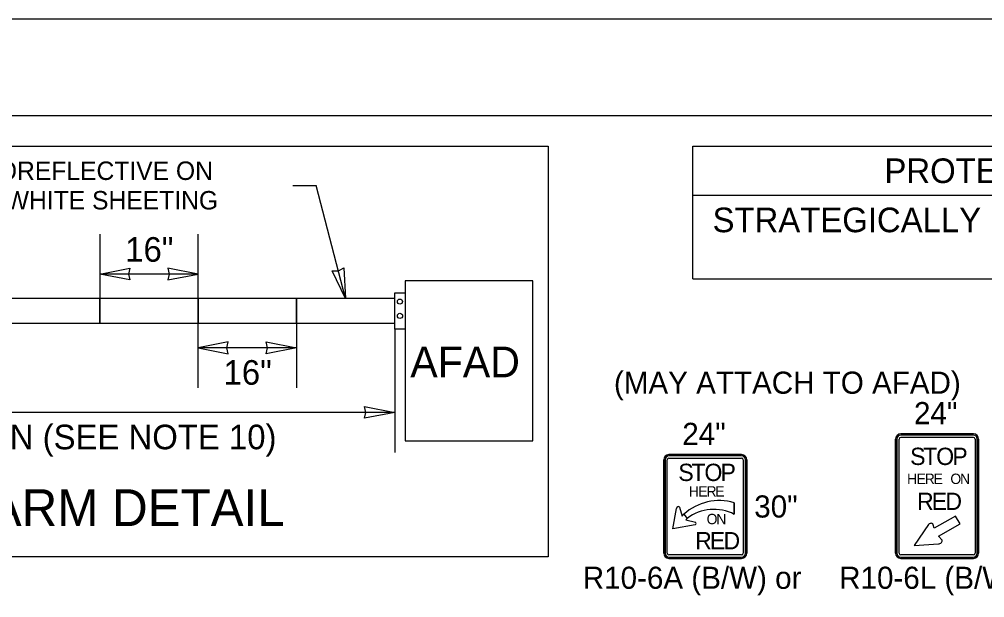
# Model space of a CAD drawing. Extents: x 99999.1 to 100095.7, y 99995 to 100010.7.
# Drawn here: x 100009.243 to 100012.384, y 100008.806 to 100010.687 of the extents above; entities that cross this region are included whole.
import ezdxf

# ---------------------------------------------------------------- set-up
doc = ezdxf.new("R2010")
doc.units = 0
for name, color, linetype in [('SH_GI_PlotLimits', 7, 'Continuous'), ('SH_GI_SheetBorder', 7, 'Continuous'), ('SH_TI_Tables', 7, 'Continuous'), ('TR_SN_ConstructionSigns', 7, 'Continuous'), ('TR_WZ_WorkZoneDetails', 7, 'Continuous')]:
    doc.layers.add(name, color=color, linetype=linetype)

msp = doc.modelspace()

# ---------------------------------------------------------------- linework, layer by layer
at = {"layer": 'SH_GI_PlotLimits'}
msp.add_lwpolyline([(99999.0625, 99999.6875), (100016.0625, 99999.6875), (100016.0625, 100010.6875), (99999.0625, 100010.6875)], close=True, dxfattribs=at)
at = {"layer": 'SH_GI_SheetBorder'}
msp.add_line((100000, 100010.375), (100015.75, 100010.375), dxfattribs=at)
at = {"layer": 'SH_TI_Tables'}
for p, q in [((100011.4347, 100009.843), (100011.4347, 100010.275)), ((100011.4347, 100010.275), (100015.65, 100010.275)), ((100011.4347, 100010.115), (100015.65, 100010.115)), ((100011.4347, 100009.843), (100015.65, 100009.843))]:
    msp.add_line(p, q, dxfattribs=at)
at = {"layer": 'TR_SN_ConstructionSigns'}
for p, q in [((100012.0939, 100009.3222), (100012.0939, 100008.951)), ((100012.0939, 100008.951), (100012.0939, 100009.3222)), ((100012.0939, 100009.3222), (100012.0939, 100008.951)), ((100012.0981, 100009.3222), (100012.0981, 100008.951)), ((100012.1052, 100008.951), (100012.1052, 100009.3222)), ((100012.347, 100009.3391), (100012.1108, 100009.3391)), ((100012.1108, 100009.3391), (100012.347, 100009.3391)), ((100012.347, 100009.3391), (100012.1108, 100009.3391)), ((100012.347, 100009.3349), (100012.1108, 100009.3349)), ((100012.1108, 100009.3279), (100012.347, 100009.3279)), ((100012.3527, 100009.3222), (100012.3527, 100008.951)), ((100012.3597, 100008.951), (100012.3597, 100009.3222)), ((100012.3639, 100008.951), (100012.3639, 100009.3222)), ((100012.3639, 100009.3222), (100012.3639, 100008.951)), ((100012.3639, 100008.951), (100012.3639, 100009.3222)), ((100011.3397, 100009.2547), (100011.3397, 100008.951)), ((100011.3397, 100008.951), (100011.3397, 100009.2547)), ((100011.3397, 100009.2547), (100011.3397, 100008.951)), ((100011.3397, 100008.951), (100011.3397, 100009.2547)), ((100011.3439, 100009.2547), (100011.3439, 100008.951)), ((100011.351, 100008.951), (100011.351, 100009.2547)), ((100011.5928, 100009.2716), (100011.3566, 100009.2716)), ((100011.3566, 100009.2716), (100011.5928, 100009.2716)), ((100011.5928, 100009.2716), (100011.3566, 100009.2716)), ((100011.3566, 100009.2716), (100011.5928, 100009.2716)), ((100011.5928, 100009.2674), (100011.3566, 100009.2674)), ((100011.3566, 100009.2604), (100011.5928, 100009.2604)), ((100011.5985, 100009.2547), (100011.5985, 100008.951)), ((100011.6055, 100008.951), (100011.6055, 100009.2547)), ((100011.6097, 100008.951), (100011.6097, 100009.2547)), ((100011.6097, 100009.2547), (100011.6097, 100008.951)), ((100011.6097, 100008.951), (100011.6097, 100009.2547)), ((100011.6097, 100009.2547), (100011.6097, 100008.951)), ((100011.3692, 100009.0297), (100011.3815, 100009.0967)), ((100011.3912, 100009.1011), (100011.3997, 100009.0719)), ((100011.5692, 100009.1152), (100011.5689, 100009.0774)), ((100011.5689, 100009.0774), (100011.5692, 100009.1152)), ((100011.3997, 100009.0719), (100011.4054, 100009.0776)), ((100011.4054, 100009.0776), (100011.4159, 100009.0642)), ((100011.4054, 100009.0776), (100011.4159, 100009.0642)), ((100011.4159, 100009.0642), (100011.4117, 100009.0599)), ((100012.289, 100009.0719), (100012.22, 100009.0321)), ((100012.3037, 100009.0463), (100012.289, 100009.0719)), ((100011.4423, 100009.0433), (100011.3692, 100009.0297)), ((100011.4117, 100009.0599), (100011.4424, 100009.0517)), ((100012.2015, 100009.0445), (100012.1541, 100008.9764)), ((100012.22, 100009.0321), (100012.2166, 100009.0435)), ((100012.234, 100009.0061), (100012.3037, 100009.0463)), ((100012.2451, 100008.9938), (100012.234, 100009.0061)), ((100012.1541, 100008.9764), (100012.2332, 100008.9819)), ((100011.5928, 100008.9454), (100011.3566, 100008.9454)), ((100011.3566, 100008.9383), (100011.5928, 100008.9383)), ((100012.347, 100008.9454), (100012.1108, 100008.9454)), ((100012.1108, 100008.9383), (100012.347, 100008.9383)), ((100011.3566, 100008.9341), (100011.5928, 100008.9341)), ((100011.5928, 100008.9341), (100011.3566, 100008.9341)), ((100011.3566, 100008.9341), (100011.5928, 100008.9341)), ((100011.5928, 100008.9341), (100011.3566, 100008.9341)), ((100012.1108, 100008.9341), (100012.347, 100008.9341)), ((100012.347, 100008.9341), (100012.1108, 100008.9341)), ((100012.1108, 100008.9341), (100012.347, 100008.9341))]:
    msp.add_line(p, q, dxfattribs=at)
for centre, radius, start, end in [((100012.1108, 100009.3222), 0.0169, 90, 180), ((100012.1108, 100009.3222), 0.0169, 90, 180), ((100012.1108, 100009.3222), 0.0169, 90, 180), ((100012.1108, 100009.3222), 0.0127, 90, 180), ((100012.1108, 100009.3222), 0.00562, 90, 180), ((100012.347, 100009.3222), 0.0169, 0, 90), ((100012.347, 100009.3222), 0.0169, 0, 90), ((100012.347, 100009.3222), 0.0169, 0, 90), ((100012.347, 100009.3222), 0.0127, 0, 90), ((100012.347, 100009.3222), 0.00562, 0, 90), ((100011.3566, 100009.2547), 0.0169, 90, 180), ((100011.3566, 100009.2547), 0.0169, 90, 180), ((100011.3566, 100009.2547), 0.0169, 90, 180), ((100011.3566, 100009.2547), 0.0169, 90, 180), ((100011.3566, 100009.2547), 0.0127, 90, 180), ((100011.3566, 100009.2547), 0.00562, 90, 180), ((100011.5928, 100009.2547), 0.0169, 0, 90), ((100011.5928, 100009.2547), 0.0169, 0, 90), ((100011.5928, 100009.2547), 0.0169, 0, 90), ((100011.5928, 100009.2547), 0.0169, 0, 90), ((100011.5928, 100009.2547), 0.0127, 0, 90), ((100011.5928, 100009.2547), 0.00562, 0, 90), ((100011.5208, 100008.9504), 0.1718, 73.6434, 132.2131), ((100011.5208, 100008.9504), 0.1718, 73.6434, 132.2131), ((100011.5028, 100008.9509), 0.1427, 62.4149, 127.4769), ((100011.5028, 100008.9509), 0.1427, 62.4149, 127.4769), ((100011.3566, 100008.951), 0.0169, 180, 270), ((100011.3566, 100008.951), 0.0169, 180, 270), ((100011.3566, 100008.951), 0.0169, 180, 270), ((100011.3566, 100008.951), 0.0169, 180, 270), ((100011.3566, 100008.951), 0.0127, 180, 270), ((100011.3566, 100008.951), 0.00562, 180, 270), ((100011.5928, 100008.951), 0.0169, 270, 0), ((100011.5928, 100008.951), 0.0169, 270, 0), ((100011.5928, 100008.951), 0.0169, 270, 0), ((100011.5928, 100008.951), 0.0127, 270, 0), ((100011.5928, 100008.951), 0.00562, 270, 0), ((100011.5928, 100008.951), 0.0169, 270, 0), ((100012.1108, 100008.951), 0.0169, 180, 270), ((100012.1108, 100008.951), 0.0169, 180, 270), ((100012.1108, 100008.951), 0.0169, 180, 270), ((100012.1108, 100008.951), 0.0127, 180, 270), ((100012.1108, 100008.951), 0.00562, 180, 270), ((100012.347, 100008.951), 0.0169, 270, 0), ((100012.347, 100008.951), 0.0169, 270, 0), ((100012.347, 100008.951), 0.0169, 270, 0), ((100012.347, 100008.951), 0.0127, 270, 0), ((100012.347, 100008.951), 0.00562, 270, 0)]:
    msp.add_arc(centre, radius, start, end, dxfattribs=at)
for centre, major_axis, ratio, start_param, end_param in [((100011.3873, 100009.0968), (-0.00583, -0.00008), 0.989437, 3.962549, 6.283185), ((100011.4403, 100009.0475), (-0.00414, 0.00215), 0.999053, 2.490568, 4.712389), ((100012.2076, 100009.0406), (0.00841, 0.00485), 0.700347, 5.977036, 8.198856), ((100012.2368, 100008.9893), (-0.00822, -0.00474), 0.700347, 0.771965, 3.092601)]:
    msp.add_ellipse(centre, major_axis=major_axis, ratio=ratio, start_param=start_param, end_param=end_param, dxfattribs=at)
at = {"layer": 'TR_WZ_WorkZoneDetails'}
for p, q in [((100010.1326, 100010.147), (100010.2088, 100010.147)), ((100010.3043, 100009.779), (100010.2088, 100010.147)), ((100009.5043, 100009.989), (100009.5043, 100009.779)), ((100009.8243, 100009.779), (100009.8243, 100009.989)), ((100009.8243, 100009.859), (100009.5043, 100009.859)), ((100009.8243, 100009.489), (100009.8243, 100009.699)), ((100010.1443, 100009.699), (100010.1443, 100009.489)), ((100010.4643, 100009.6797), (100010.4643, 100009.279)), ((100010.1443, 100009.619), (100009.8243, 100009.619)), ((100010.4643, 100009.409), (100008.6643, 100009.409))]:
    msp.add_line(p, q, dxfattribs=at)
for points in [[(100007.6374, 100010.275), (100010.9639, 100010.275), (100010.9639, 100008.939), (100007.6374, 100008.939)], [(100009.5043, 100009.859), (100009.6026, 100009.8783), (100009.5981, 100009.859), (100009.6026, 100009.8397)], [(100009.8243, 100009.859), (100009.7261, 100009.8783), (100009.7306, 100009.859), (100009.7261, 100009.8397)], [(100010.3043, 100009.779), (100010.2611, 100009.8693), (100010.2809, 100009.8697), (100010.2984, 100009.879)], [(100010.4643, 100009.7983), (100010.4977, 100009.7983), (100010.4977, 100009.6797), (100010.4643, 100009.6797)], [(100009.8243, 100009.619), (100009.9226, 100009.5997), (100009.9181, 100009.619), (100009.9226, 100009.6383)], [(100010.1443, 100009.619), (100010.0461, 100009.5997), (100010.0506, 100009.619), (100010.0461, 100009.6383)], [(100010.4643, 100009.409), (100010.3661, 100009.3897), (100010.3706, 100009.409), (100010.3661, 100009.4283)]]:
    msp.add_lwpolyline(points, close=True, dxfattribs=at)
for points in [[(100010.4977, 100009.6797), (100010.4977, 100009.3163), (100010.9139, 100009.3163), (100010.9139, 100009.8374), (100010.4977, 100009.8374), (100010.4977, 100009.7983), (100010.4977, 100009.6797)], [(100010.9139, 100009.8374), (100010.4977, 100009.8374), (100010.4977, 100009.3163), (100010.9139, 100009.3163), (100010.9139, 100009.8374)], [(100010.4643, 100009.779), (100008.6643, 100009.779), (100008.6643, 100009.699), (100010.4643, 100009.699), (100010.4643, 100009.779)], [(100009.1843, 100009.699), (100009.5043, 100009.699), (100009.5043, 100009.779), (100009.1843, 100009.779), (100009.1843, 100009.699)], [(100009.5043, 100009.699), (100009.8243, 100009.699), (100009.8243, 100009.779), (100009.5043, 100009.779), (100009.5043, 100009.699)], [(100009.8243, 100009.699), (100010.1443, 100009.699), (100010.1443, 100009.779), (100009.8243, 100009.779), (100009.8243, 100009.699)], [(100010.1443, 100009.699), (100010.4643, 100009.699), (100010.4643, 100009.779), (100010.1443, 100009.779), (100010.1443, 100009.699)]]:
    msp.add_lwpolyline(points, dxfattribs=at)
for centre, radius in [((100010.4813, 100009.7693), 0.00828), ((100010.4813, 100009.7229), 0.00855)]:
    msp.add_circle(centre, radius, dxfattribs=at)

# ---------------------------------------------------------------- texts
at = {"layer": 'SH_TI_Tables'}
for s, p in [('PROTECTIVE VEHICLE ROLL AHEAD DISTANCE = R', (100012.0577, 100010.155)), ('STRATEGICALLY POSITION WORK VEHICLE TO PROTECT WORK CREW.', (100011.4984, 100009.995))]:
    msp.add_text(s, height=0.08, dxfattribs=at).set_placement(p)
at = {"layer": 'TR_SN_ConstructionSigns'}
for s, p in [('(MAY ATTACH TO AFAD)', (100011.1775, 100009.4696)), ('24"', (100012.1539, 100009.3706)), ('24"', (100011.3999, 100009.3031)), ('30"', (100011.634, 100009.0669)), ('R10-6A (B/W) or', (100011.0761, 100008.8351)), ('R10-6L (B/W)', (100011.9104, 100008.8351))]:
    msp.add_text(s, height=0.072, rotation=360, dxfattribs=at).set_placement(p)
for s, height, p in [('S', 0.0562, (100012.1412, 100009.2379)), ('T', 0.0562, (100012.1839, 100009.2379)), ('O', 0.0562, (100012.2261, 100009.2379)), ('P', 0.0562, (100012.2784, 100009.2379)), ('S', 0.0562, (100011.387, 100009.1858)), ('T', 0.0562, (100011.4297, 100009.1858)), ('O', 0.0562, (100011.4719, 100009.1858)), ('P', 0.0562, (100011.5242, 100009.1858)), ('H', 0.0338, (100012.1312, 100009.176)), ('E', 0.0338, (100012.1623, 100009.176)), ('R', 0.0338, (100012.1889, 100009.176)), ('E', 0.0338, (100012.2176, 100009.176)), ('O', 0.0338, (100012.2723, 100009.176)), ('N', 0.0338, (100012.3037, 100009.176)), ('H', 0.0338, (100011.421, 100009.1352)), ('E', 0.0338, (100011.4521, 100009.1352)), ('R', 0.0338, (100011.4788, 100009.1352)), ('E', 0.0338, (100011.5074, 100009.1352)), ('R', 0.0562, (100012.1637, 100009.0916)), ('E', 0.0562, (100012.2115, 100009.0916)), ('D', 0.0562, (100012.2559, 100009.0916)), ('O', 0.0338, (100011.4791, 100009.0452)), ('N', 0.0338, (100011.5105, 100009.0452)), ('R', 0.0562, (100011.4417, 100008.9636)), ('E', 0.0562, (100011.4895, 100008.9636)), ('D', 0.0562, (100011.5339, 100008.9636))]:
    msp.add_text(s, height=height, dxfattribs=at).set_placement(p)
at = {"layer": 'TR_WZ_WorkZoneDetails'}
for s, height, p in [('GATE ARM SHALL BE FULLY RETROREFLECTIVE ON', 0.06, (100007.8352, 100010.165)), ('BOTH SIDES WITH ALTERNATING RED/WHITE SHEETING', 0.06, (100007.6874, 100010.069)), ('16"', 0.08, (100009.5873, 100009.899)), ('AFAD', 0.1, (100010.5149, 100009.5231)), ('16"', 0.08, (100009.9073, 100009.499)), ('78" MIN (SEE NOTE 10)', 0.08, (100008.9061, 100009.289))]:
    msp.add_text(s, height=height, dxfattribs=at).set_placement(p)
msp.add_text('AFAD GATE ARM DETAIL', height=0.12, rotation=360, dxfattribs=at).set_placement((100008.1893, 100009.039))

doc.saveas('drawing.dxf')
